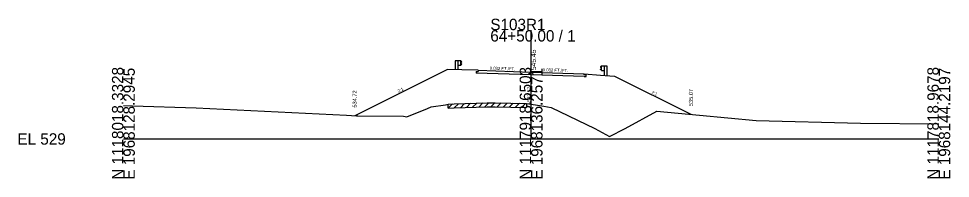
# Model space of a CAD drawing. Extents: x -26 to 203, y -10 to 12018.
# Drawn here: x -25.7 to 202.8, y 4990.3 to 5029.6 of the extents above; entities that cross this region are included whole.
import ezdxf

# ---------------------------------------------------------------- set-up
doc = ezdxf.new("R2010")
doc.units = 0
for name, color, linetype in [('Level 10', 7, 'Continuous'), ('Level 11', 7, 'Continuous'), ('Level 12', 7, 'Continuous'), ('Level 24', 7, 'Continuous'), ('Level 32', 7, 'Continuous'), ('Level 33', 7, 'Continuous'), ('Level 59', 7, 'Continuous'), ('Level 6', 7, 'Continuous'), ('Level 60', 7, 'Continuous'), ('Level 61', 7, 'Continuous'), ('Level 63', 7, 'Continuous'), ('Level 7', 7, 'Continuous')]:
    doc.layers.add(name, color=color, linetype=linetype)

msp = doc.modelspace()

# ---------------------------------------------------------------- linework, layer by layer
at = {"layer": 'Level 11'}
for p, q in [((113, 5015.73), (113, 5016.04)), ((113.5, 5015.72), (113, 5015.73)), ((113, 5015.37), (113.5, 5015.36)), ((113.5, 5015.36), (113.5, 5015.72))]:
    msp.add_line(p, q, dxfattribs=at)
at = {"layer": 'Level 12'}
for p, q in [((86.5, 5016.57), (87, 5016.55)), ((86.5, 5016.57), (86.5, 5016.21)), ((87, 5016.87), (87, 5016.55)), ((100, 5015.78), (86.5, 5016.21)), ((113, 5015.37), (100, 5015.78))]:
    msp.add_line(p, q, dxfattribs=at)
at = {"layer": 'Level 24'}
for p, q in [((81.4, 5019.24), (81.4, 5017.04)), ((82.06, 5019.24), (81.4, 5019.24)), ((82.06, 5019.24), (82.06, 5017.02)), ((82.73, 5019.24), (82.06, 5019.24)), ((82.73, 5018.07), (82.73, 5019.24)), ((82.73, 5019.17), (83, 5018.97)), ((83, 5018.92), (82.73, 5018.72)), ((83, 5018.4), (82.73, 5018.6)), ((83, 5018.97), (83, 5018.92)), ((82.73, 5018.07), (82.06, 5018.07)), ((82.73, 5018.15), (83, 5018.35)), ((83, 5018.35), (83, 5018.4)), ((117.27, 5017.89), (117, 5017.69)), ((117, 5017.69), (117, 5017.64)), ((117, 5017.64), (117.27, 5017.44)), ((117, 5017.12), (117.27, 5017.32)), ((117, 5017.07), (117, 5017.12)), ((117.27, 5016.87), (117, 5017.07)), ((117.27, 5016.79), (117.27, 5017.96)), ((117.27, 5017.96), (117.94, 5017.96)), ((117.27, 5016.79), (117.94, 5016.79)), ((117.94, 5017.96), (117.94, 5015.63)), ((117.94, 5017.96), (118.6, 5017.96)), ((118.6, 5017.96), (118.6, 5015.58))]:
    msp.add_line(p, q, dxfattribs=at)
at = {"layer": 'Level 59'}
for p, q in [((87, 5016.87), (100, 5016.45)), ((100, 5016.45), (113, 5016.04))]:
    msp.add_line(p, q, dxfattribs=at)
at = {"layer": 'Level 6'}
for p, q in [((83, 5016.99), (79.5, 5017.1)), ((87, 5016.87), (83, 5016.99)), ((113, 5016.04), (117, 5015.71)), ((117, 5015.71), (120.5, 5015.42))]:
    msp.add_line(p, q, dxfattribs=at)
at = {"layer": 'Level 60'}
for p, q in [((0, 5008.21), (2.24, 5008.17)), ((2.24, 5008.17), (17.83, 5007.64)), ((17.83, 5007.64), (54.74, 5005.81)), ((69.56, 5005.47), (74.56, 5007.51)), ((74.56, 5007.51), (75.48, 5007.87)), ((75.48, 5007.87), (79, 5008.42)), ((79, 5008.42), (79.65, 5008.56)), ((79.65, 5008.56), (81.12, 5008.62)), ((81.12, 5008.62), (89.25, 5008.91)), ((89.25, 5008.91), (91.17, 5008.89)), ((91.17, 5008.89), (98.87, 5008.75)), ((98.87, 5008.75), (100, 5008.57)), ((100, 5008.57), (103.11, 5008.06)), ((103.11, 5008.06), (104.93, 5007.75)), ((104.93, 5007.75), (115.67, 5002.54)), ((54.74, 5005.81), (57.2, 5005.7)), ((57.2, 5005.7), (57.52, 5005.69)), ((57.52, 5005.69), (68.72, 5005.57)), ((68.72, 5005.57), (69.56, 5005.47)), ((123.07, 5002.57), (130.88, 5006.8)), ((130.88, 5006.8), (141.3, 5005.88)), ((141.3, 5005.88), (155.22, 5004.51)), ((155.22, 5004.51), (180.83, 5003.88)), ((180.83, 5003.88), (200, 5003.68)), ((115.67, 5002.54), (119.25, 5000.6)), ((119.25, 5000.6), (123.07, 5002.57))]:
    msp.add_line(p, q, dxfattribs=at)
at = {"layer": 'Level 61'}
for p, q in [((79.65, 5007.56), (80.69, 5008.61)), ((79.65, 5007.56), (79.65, 5008.56)), ((79.65, 5007.56), (81.12, 5007.62)), ((81.12, 5007.62), (89.25, 5007.91)), ((81.15, 5007.62), (82.18, 5008.66)), ((82.65, 5007.68), (83.68, 5008.71)), ((84.15, 5007.73), (85.18, 5008.77)), ((85.65, 5007.78), (86.68, 5008.82)), ((87.15, 5007.84), (88.18, 5008.87)), ((88.65, 5007.89), (89.66, 5008.91)), ((89.25, 5007.91), (91.17, 5007.89)), ((90.15, 5007.9), (91.13, 5008.89)), ((91.17, 5007.89), (98.87, 5007.75)), ((91.65, 5007.88), (92.63, 5008.86)), ((93.15, 5007.85), (94.13, 5008.83)), ((94.65, 5007.82), (95.63, 5008.81)), ((96.15, 5007.8), (97.13, 5008.78)), ((97.65, 5007.77), (98.63, 5008.75)), ((98.87, 5008.75), (98.87, 5007.75))]:
    msp.add_line(p, q, dxfattribs=at)
at = {"layer": 'Level 63'}
for p, q in [((100, 5000), (100, 5026.74)), ((0, 5000), (100, 5000)), ((100, 5000), (200, 5000))]:
    msp.add_line(p, q, dxfattribs=at)
at = {"layer": 'Level 7'}
for p, q in [((79.5, 5017.1), (56.74, 5005.72)), ((120.5, 5015.42), (139.2, 5006.07))]:
    msp.add_line(p, q, dxfattribs=at)

# ---------------------------------------------------------------- texts
at = {"layer": 'Level 10'}
msp.add_text(' 537.57', height=0.9, rotation=90, dxfattribs=at).set_placement((99.95, 5008.71))
at = {"layer": 'Level 32'}
for s, rotation, p in [('0.032 FT./FT.', 358.1901, (89.84, 5017.03)), ('0.032 FT./FT.', 358.1901, (102.84, 5016.62)), ('2:1', 26.5651, (67.5, 5011.38)), ('2:1', 333.4349, (129.46, 5011.22))]:
    msp.add_text(s, height=0.75, rotation=rotation, dxfattribs=at).set_placement(p)
at = {"layer": 'Level 33'}
for s, p in [('534.72', (57.24, 5007.72)), ('535.07', (139.7, 5008.07))]:
    msp.add_text(s, height=1, rotation=90, dxfattribs=at).set_placement(p)
at = {"layer": 'Level 59'}
msp.add_text(' 545.45', height=1.2, rotation=90, dxfattribs=at).set_placement((101.2, 5016.45))
at = {"layer": 'Level 63'}
for s, p in [('S103R1', (90, 5026.74)), ('64+50.00 / 1', (90, 5023.94)), ('EL 529', (-26, 4998.6))]:
    msp.add_text(s, height=2.8, dxfattribs=at).set_placement(p)
for s, p in [('N 1118018.3328', (0, 4990)), ('E 1968128.2945', (2.8, 4990)), ('N 1117918.6503', (100, 4990)), ('E 1968136.2571', (102.8, 4990)), ('N 1117818.9678', (200, 4990)), ('E 1968144.2197', (202.8, 4990))]:
    msp.add_text(s, height=2.8, rotation=90, dxfattribs=at).set_placement(p)

doc.saveas('drawing.dxf')
